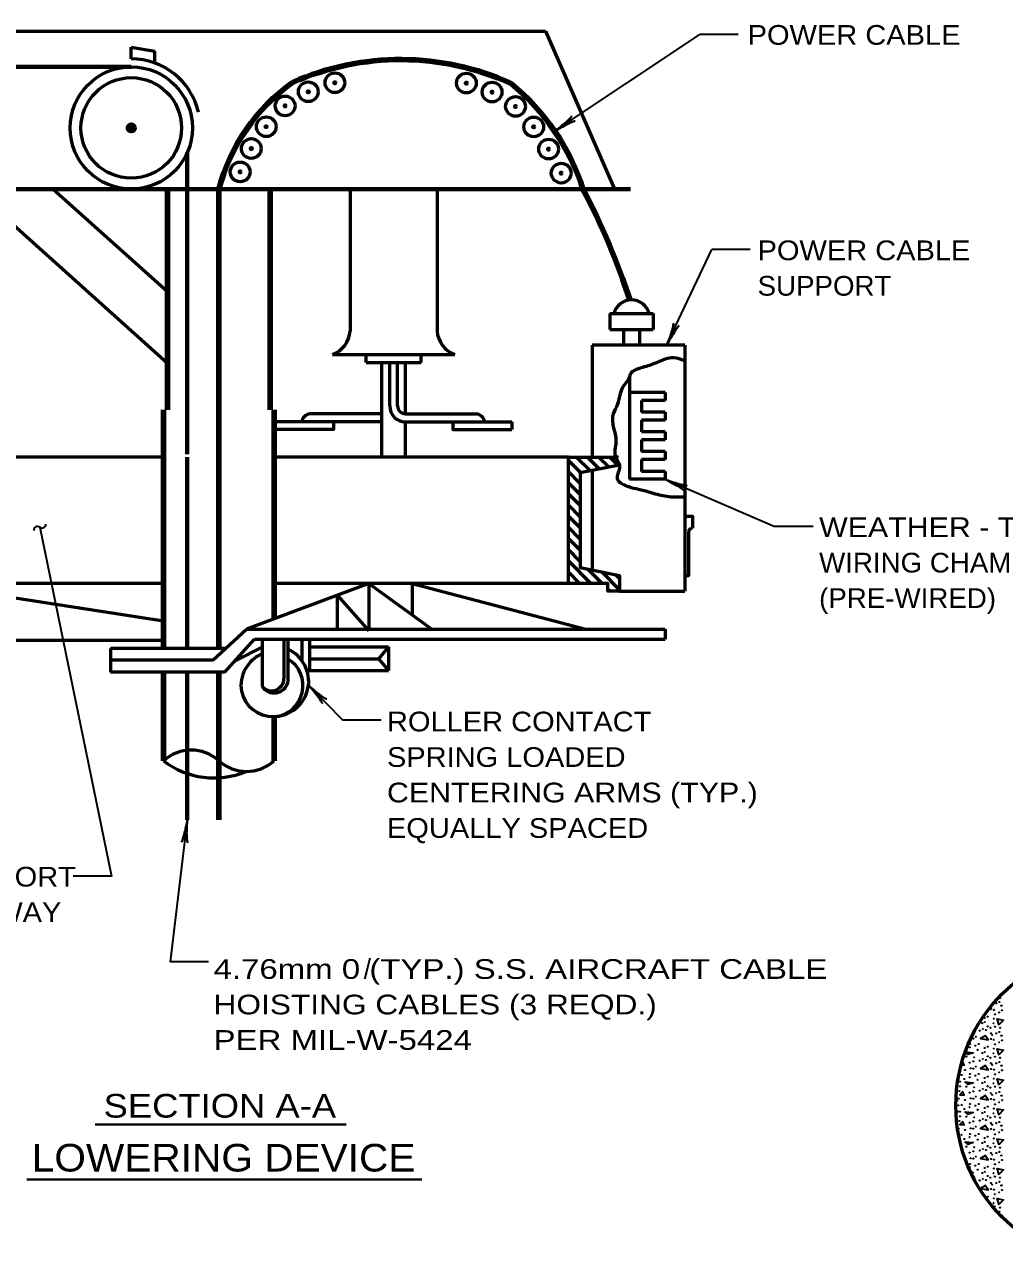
# Model space of a CAD drawing. Extents: x -24 to 689, y -7 to 446.
# Drawn here: x 208.2 to 332.4, y 109.6 to 266.6 of the extents above; entities that cross this region are included whole.
import ezdxf
from ezdxf.enums import TextEntityAlignment as Align

# ---------------------------------------------------------------- set-up
doc = ezdxf.new("R2010")
doc.units = 0
doc.header["$PDMODE"] = 32
doc.header["$PDSIZE"] = 0.5
doc.layers.add('1', color=7, linetype='Continuous', lineweight=35)

msp = doc.modelspace()

# ---------------------------------------------------------------- hatches: boundary and pattern name
at = {"layer": '1'}
for points in [[(247.661, 259.304, 1), (247.411, 259.304, 1)], [(264.325, 259.26, 1), (264.075, 259.26, 1)], [(244.293, 258.151, 1), (244.043, 258.151, 1)], [(267.586, 258.116, 1), (267.336, 258.116, 1)], [(241.357, 256.358, 1), (241.107, 256.358, 1)], [(270.557, 256.295, 1), (270.307, 256.295, 1)], [(222.233, 253.567, 1), (221.233, 253.567, 1)], [(238.965, 253.726, 1), (238.715, 253.726, 1)], [(272.86, 253.701, 1), (272.61, 253.701, 1)], [(237.069, 250.956, 1), (236.819, 250.956, 1)], [(274.748, 250.886, 1), (274.498, 250.886, 1)], [(235.657, 247.993, 1), (235.407, 247.993, 1)], [(276.345, 247.833, 1), (276.095, 247.833, 1)]]:
    msp.add_hatch(color=256, dxfattribs=at).paths.add_polyline_path(points)

# ---------------------------------------------------------------- linework, layer by layer
at = {"layer": '1', "lineweight": 53}
for p, q in [((194.233, 265.817), (274.233, 265.817)), ((274.233, 265.817), (282.983, 245.817)), ((221.733, 262.317), (221.733, 263.817)), ((221.733, 263.817), (224.733, 263.317)), ((224.733, 261.787), (224.733, 263.317)), ((201.721, 245.817), (226.335, 223.749)), ((211.835, 245.817), (226.335, 232.817)), ((249.483, 245.817), (249.483, 227.817)), ((260.483, 245.817), (260.483, 227.817)), ((282.378, 230.022), (287.878, 230.022)), ((282.378, 230.022), (282.378, 228.022)), ((287.878, 230.022), (287.878, 228.022)), ((282.378, 228.022), (287.878, 228.022)), ((284.128, 228.022), (284.128, 226.022)), ((286.128, 228.022), (286.128, 226.022)), ((247.233, 224.817), (262.733, 224.817)), ((251.483, 223.817), (251.483, 224.817)), ((258.483, 223.817), (258.483, 224.817)), ((291.878, 226.022), (280.128, 226.022)), ((280.128, 226.022), (280.128, 211.817)), ((291.878, 226.022), (291.878, 194.817)), ((251.483, 223.817), (258.483, 223.817)), ((253.483, 211.817), (253.483, 223.817)), ((254.483, 218.317), (254.483, 223.817)), ((255.483, 218.317), (255.483, 223.817)), ((256.483, 217.317), (256.483, 223.817)), ((284.878, 222.022), (284.878, 209.022)), ((289.378, 220.022), (284.878, 220.022)), ((289.378, 220.022), (289.378, 219.022)), ((289.378, 219.022), (286.378, 219.022)), ((286.378, 219.022), (286.378, 217.522)), ((253.483, 217.317), (244.353, 217.317)), ((256.483, 217.317), (265.483, 217.317)), ((289.378, 217.522), (286.378, 217.522)), ((289.378, 217.522), (289.378, 216.522)), ((239.853, 216.317), (239.853, 215.317)), ((253.483, 216.317), (239.853, 216.317)), ((256.483, 216.317), (269.983, 216.317)), ((256.483, 211.817), (256.483, 216.317)), ((269.983, 216.317), (269.983, 215.317)), ((289.378, 216.522), (286.378, 216.522)), ((286.378, 216.522), (286.378, 215.022)), ((289.378, 215.022), (286.378, 215.022)), ((289.378, 214.022), (286.378, 214.022)), ((286.378, 214.022), (286.378, 212.522)), ((289.378, 215.022), (289.378, 214.022)), ((289.378, 212.522), (286.378, 212.522)), ((289.378, 212.522), (289.378, 211.522)), ((225.835, 211.817), (196.233, 211.817)), ((277.128, 211.817), (239.835, 211.817)), ((278.707, 209.833), (277.128, 211.412)), ((279.886, 210.069), (278.137, 211.817)), ((281.064, 210.304), (279.552, 211.817)), ((282.243, 210.54), (280.966, 211.817)), ((283.421, 210.776), (282.38, 211.817)), ((289.378, 211.522), (286.378, 211.522)), ((286.378, 211.522), (286.378, 210.022)), ((278.628, 208.498), (277.128, 209.998)), ((280.128, 210.117), (280.128, 197.517)), ((289.378, 209.022), (284.878, 209.022)), ((289.378, 210.022), (286.378, 210.022)), ((289.378, 210.022), (289.378, 209.022)), ((278.628, 207.084), (277.128, 208.584)), ((278.628, 205.67), (277.128, 207.17)), ((278.628, 204.256), (277.128, 205.756)), ((278.628, 202.841), (277.128, 204.341)), ((278.628, 201.427), (277.128, 202.927)), ((278.628, 200.013), (277.128, 201.513)), ((278.628, 198.599), (277.128, 200.099)), ((279.995, 195.817), (277.128, 198.684)), ((278.581, 195.817), (277.128, 197.27)), ((281.409, 195.817), (279.605, 197.622)), ((283.628, 195.013), (281.373, 197.268)), ((283.628, 196.427), (283.14, 196.915)), ((195.233, 195.817), (225.835, 191.067)), ((225.835, 195.817), (196.233, 195.817)), ((251.835, 195.817), (236.335, 190.005)), ((277.128, 195.817), (239.835, 195.817)), ((251.835, 195.817), (251.835, 189.817)), ((251.835, 195.817), (259.828, 190.005)), ((257.335, 195.817), (257.335, 191.817)), ((257.335, 195.817), (279.328, 190.005)), ((277.167, 195.817), (277.128, 195.856)), ((282.409, 194.817), (282.128, 195.099)), ((283.628, 194.817), (291.878, 194.817)), ((247.835, 194.317), (247.835, 189.817)), ((247.835, 194.317), (251.835, 189.817)), ((225.835, 188.567), (164.733, 188.567)), ((232.085, 186.067), (236.335, 190.005)), ((233.585, 184.567), (237.335, 188.755)), ((236.335, 190.005), (289.378, 190.005)), ((237.335, 188.755), (289.378, 188.755)), ((238.335, 188.755), (238.335, 182.755)), ((241.085, 188.755), (241.085, 183.755)), ((241.585, 188.755), (241.585, 183.255)), ((243.335, 188.755), (243.335, 186.092)), ((244.335, 188.755), (244.335, 184.755)), ((289.378, 190.005), (289.378, 188.755)), ((233.704, 187.567), (219.085, 187.567)), ((219.085, 187.567), (219.085, 184.567)), ((238.335, 187.709), (234.878, 186.01)), ((244.335, 187.755), (254.335, 187.755)), ((254.335, 187.755), (254.335, 184.755)), ((232.085, 186.067), (219.085, 186.067)), ((244.335, 186.255), (253.085, 186.255)), ((233.585, 184.567), (219.085, 184.567)), ((244.016, 184.755), (254.335, 184.755))]:
    msp.add_line(p, q, dxfattribs=at)
at = {"layer": '1'}
for p, q in [((275.388, 253.162), (293.808, 265.43)), ((298.666, 265.43), (293.808, 265.43)), ((289.577, 226.022), (295.324, 238.144)), ((300.181, 238.144), (295.324, 238.144)), ((289.378, 209.022), (303.279, 203.025)), ((308.137, 203.025), (303.279, 203.025)), ((244.191, 182.927), (248.548, 178.457)), ((253.405, 178.457), (248.548, 178.457)), ((228.835, 165.817), (226.651, 147.826)), ((231.508, 147.826), (226.651, 147.826)), ((327.108, 135.18), (327.029, 135.097))]:
    msp.add_line(p, q, dxfattribs=at)
at = {"layer": '1', "lineweight": 70}
for p, q in [((200.233, 261.317), (221.733, 261.317)), ((228.835, 212.197), (228.835, 250.466)), ((239.335, 245.817), (284.983, 245.817)), ((228.835, 187.567), (228.835, 211.815)), ((228.835, 165.817), (228.835, 184.567))]:
    msp.add_line(p, q, dxfattribs=at)
at = {"layer": '1', "lineweight": 200}
for p, q in [((226.335, 217.817), (226.335, 245.817)), ((232.835, 187.567), (232.835, 245.817)), ((239.335, 217.817), (239.335, 245.817)), ((225.835, 187.567), (225.835, 217.817)), ((239.835, 191.317), (239.835, 217.817)), ((225.835, 173.317), (225.835, 184.567)), ((232.835, 165.817), (232.835, 184.567)), ((239.835, 173.317), (239.835, 178.92))]:
    msp.add_line(p, q, dxfattribs=at)
at = {"layer": '1', "lineweight": 40}
for p, q in [((217.135, 127.196), (248.977, 127.196)), ((208.484, 120.206), (258.561, 120.206))]:
    msp.add_line(p, q, dxfattribs=at)
at = {"layer": '1', "lineweight": 70}
msp.add_lwpolyline([(183.483, 245.817), (228.835, 245.817), (239.335, 245.817)], dxfattribs=at)
at = {"layer": '1', "lineweight": 53}
for points in [[(247.353, 216.317), (247.353, 215.317), (239.853, 215.317)], [(262.483, 216.317), (262.483, 215.317), (269.983, 215.317)], [(277.128, 195.817), (277.128, 211.817), (283.128, 211.817)], [(283.628, 210.817), (278.628, 209.817), (278.628, 197.817), (283.628, 196.817), (283.628, 194.817), (282.128, 194.817), (282.128, 195.817), (277.128, 195.817)], [(291.878, 204.317), (292.878, 204.317), (292.878, 202.817)], [(291.878, 196.817), (292.378, 196.817), (292.378, 202.317)], [(254.335, 187.755), (253.085, 186.255), (254.335, 184.755)]]:
    msp.add_lwpolyline(points, dxfattribs=at)
at = {"layer": '1'}
for points in [[(210.138, 202.928), (219.214, 158.699), (214.356, 158.699)], [(331.728, 139.8), (331.488, 140.6), (332.268, 140.44), (331.708, 139.84)], [(330.008, 138.46), (329.348, 138.1), (330.328, 137.92), (329.968, 138.48)], [(331.728, 136), (331.488, 136.8), (332.268, 136.64), (331.708, 136.04)], [(326.94, 134.765), (327.308, 134.74), (327.108, 135.14)], [(327.454, 136.412), (328.428, 136.3), (327.748, 136.06), (327.438, 136.37)], [(330.008, 134.66), (329.348, 134.3), (330.328, 134.12), (329.968, 134.68)], [(331.728, 132.2), (331.488, 133), (332.268, 132.84), (331.708, 132.24)], [(327.108, 131.38), (326.728, 130.98), (327.308, 130.94), (327.108, 131.34)], [(330.008, 130.86), (329.348, 130.5), (330.328, 130.32), (329.968, 130.88)], [(331.728, 128.4), (331.488, 129.2), (332.268, 129.04), (331.708, 128.44)], [(327.108, 127.58), (326.728, 127.18), (327.308, 127.14), (327.108, 127.54)], [(330.008, 127.06), (329.348, 126.7), (330.328, 126.52), (329.968, 127.08)], [(331.728, 124.6), (331.488, 125.4), (332.268, 125.24), (331.708, 124.64)], [(327.247, 123.344), (327.308, 123.34), (327.157, 123.641)], [(330.008, 123.26), (329.348, 122.9), (330.328, 122.72), (329.968, 123.28)], [(328.138, 121.133), (328.428, 121.1), (328.197, 121.018)], [(331.728, 120.8), (331.488, 121.6), (332.268, 121.44), (331.708, 120.84)], [(330.008, 119.46), (329.348, 119.1), (330.328, 118.92), (329.968, 119.48)], [(331.728, 117), (331.488, 117.8), (332.268, 117.64), (331.708, 117.04)]]:
    msp.add_lwpolyline(points, dxfattribs=at)
for points in [[(327.388, 132.62), (328.428, 132.5), (327.748, 132.26)], [(327.388, 128.82), (328.428, 128.7), (327.748, 128.46)], [(327.388, 125.02), (328.428, 124.9), (327.748, 124.66)]]:
    msp.add_lwpolyline(points, close=True, dxfattribs=at)
at = {"layer": '1', "lineweight": 53}
for centre, radius in [((221.733, 253.567), 7.75), ((221.733, 253.567), 6.375), ((244.168, 258.151), 1.25), ((247.536, 259.304), 1.25), ((247.536, 259.304), 0.125), ((264.2, 259.26), 1.25), ((264.2, 259.26), 0.125), ((267.461, 258.116), 1.25), ((241.232, 256.358), 1.25), ((244.168, 258.151), 0.125), ((267.461, 258.116), 0.125), ((241.232, 256.358), 0.125), ((270.432, 256.295), 1.25), ((270.432, 256.295), 0.125), ((238.84, 253.726), 1.25), ((272.735, 253.701), 1.25), ((221.733, 253.567), 0.5), ((238.84, 253.726), 0.125), ((272.735, 253.701), 0.125), ((236.944, 250.956), 1.25), ((274.623, 250.886), 1.25), ((236.944, 250.956), 0.125), ((274.623, 250.886), 0.125), ((235.532, 247.993), 1.25), ((276.22, 247.833), 1.25), ((235.532, 247.993), 0.125), ((276.22, 247.833), 0.125), ((346.236, 129.608), 20)]:
    msp.add_circle(centre, radius, dxfattribs=at)
at = {"layer": '1'}
for centre in [(331.849, 143.256), (330.683, 141.829), (331.067, 141.737), (331.359, 142.572), (331.73, 141.405), (331.756, 142.731), (331.982, 142.267), (332.035, 142.267), (332.101, 141.684), (329.596, 140.053), (329.874, 140.689), (329.914, 140.199), (330.285, 140.862), (331.014, 140.026), (331.054, 140.623), (331.187, 141.167), (328.774, 138.321), (329.265, 139.103), (329.662, 139.297), (330.06, 139.17), (330.259, 139.655), (330.617, 139.456), (330.683, 138.772), (330.842, 138.56), (331.2, 139.602), (331.359, 138.772), (331.756, 138.931), (331.849, 139.456), (331.982, 138.467), (332.035, 138.467), (327.979, 136.995), (328.032, 137.393), (328.456, 138.083), (328.721, 137.181), (329, 136.664), (329.119, 137.393), (329.874, 136.889), (330.285, 137.062), (330.683, 138.029), (331.054, 136.823), (331.067, 137.937), (331.187, 137.367), (331.73, 137.605), (332.101, 137.884), (327.569, 135.802), (328.006, 135.038), (328.456, 135.21), (328.562, 135.723), (329.265, 135.303), (329.596, 136.253), (329.662, 135.497), (329.914, 136.399), (330.06, 135.37), (330.259, 135.855), (330.617, 135.656), (331.014, 136.226), (331.2, 135.802), (331.756, 135.131), (331.849, 135.656), (326.972, 133.487), (327.396, 134.097), (328.032, 133.593), (328.112, 134.322), (328.456, 134.283), (328.774, 134.521), (329.119, 133.593), (330.683, 134.972), (330.683, 134.229), (330.842, 134.76), (331.067, 134.137), (331.187, 133.567), (331.359, 134.972), (331.73, 133.805), (331.982, 134.667), (332.035, 134.667), (332.101, 134.084), (326.534, 132.623), (326.76, 132.639), (326.76, 132.042), (327.303, 132.97), (327.569, 132.002), (327.979, 133.195), (328.562, 131.923), (328.721, 133.381), (329, 132.864), (329.596, 132.453), (329.874, 133.089), (329.914, 132.599), (330.259, 132.055), (330.285, 133.262), (331.014, 132.426), (331.054, 133.023), (331.2, 132.002), (326.381, 130.549), (326.614, 130.469), (326.667, 131.45), (328.006, 131.238), (328.112, 130.522), (328.456, 131.41), (328.456, 130.483), (328.774, 130.721), (329.265, 131.503), (329.662, 131.697), (330.06, 131.57), (330.617, 131.856), (330.683, 131.172), (330.683, 130.429), (330.842, 130.96), (331.067, 130.337), (331.359, 131.172), (331.756, 131.331), (331.849, 131.856), (331.982, 130.867), (332.035, 130.867), (326.395, 130.231), (326.534, 128.823), (326.554, 129.634), (326.76, 128.839), (326.972, 129.687), (327.303, 129.17), (327.396, 130.297), (327.979, 129.395), (328.032, 129.793), (328.721, 129.581), (329, 129.064), (329.119, 129.793), (329.874, 129.289), (329.914, 128.799), (330.285, 129.462), (331.054, 129.223), (331.187, 129.767), (331.73, 130.005), (332.101, 130.284), (326.667, 127.65), (326.76, 128.242), (327.569, 128.202), (328.006, 127.438), (328.456, 127.61), (328.562, 128.123), (329.265, 127.703), (329.596, 128.653), (329.662, 127.897), (330.06, 127.77), (330.259, 128.255), (330.617, 128.056), (330.683, 127.372), (331.014, 128.626), (331.2, 128.202), (331.359, 127.372), (331.756, 127.531), (331.849, 128.056), (326.614, 126.669), (326.972, 125.887), (327.396, 126.497), (328.032, 125.993), (328.112, 126.722), (328.456, 126.683), (328.721, 125.781), (328.774, 126.921), (329.119, 125.993), (330.285, 125.662), (330.683, 126.629), (330.842, 127.16), (331.067, 126.537), (331.187, 125.967), (331.73, 126.205), (331.982, 127.067), (332.035, 127.067), (332.101, 126.484), (327.303, 125.37), (327.569, 124.402), (327.979, 125.595), (328.562, 124.323), (329, 125.264), (329.596, 124.853), (329.662, 124.097), (329.874, 125.489), (329.914, 124.999), (330.259, 124.455), (330.617, 124.256), (331.014, 124.826), (331.054, 125.423), (331.2, 124.402), (331.849, 124.256), (328.006, 123.638), (328.112, 122.922), (328.456, 123.81), (328.456, 122.883), (328.774, 123.121), (329.265, 123.903), (330.06, 123.97), (330.683, 123.572), (330.683, 122.829), (330.842, 123.36), (331.067, 122.737), (331.359, 123.572), (331.756, 123.731), (331.982, 123.267), (332.035, 123.267), (332.101, 122.684), (327.979, 121.795), (328.032, 122.193), (328.721, 121.981), (329, 121.464), (329.119, 122.193), (329.596, 121.053), (329.874, 121.689), (329.914, 121.199), (330.285, 121.862), (331.014, 121.026), (331.054, 121.623), (331.187, 122.167), (331.73, 122.405), (328.562, 120.523), (329.265, 120.103), (329.662, 120.297), (330.06, 120.17), (330.259, 120.655), (330.617, 120.456), (330.683, 119.772), (330.842, 119.56), (331.2, 120.602), (331.359, 119.772), (331.756, 119.931), (331.849, 120.456), (331.982, 119.467), (332.035, 119.467), (330.285, 118.062), (330.683, 119.029), (331.054, 117.823), (331.067, 118.937), (331.187, 118.367), (331.73, 118.605), (332.101, 118.884), (331.014, 117.226), (331.2, 116.802), (331.849, 116.656), (331.756, 116.131), (331.982, 115.667), (332.035, 115.667)]:
    msp.add_circle(centre, 0.0265, dxfattribs=at)
at = {"layer": '1', "lineweight": 53}
for centre, radius, start, end in [((221.733, 253.567), 8.75, 13.21298, 90), ((285.128, 229.451), 2.321, 14.25003, 165.74997), ((245.99, 228.093), 3.503, 290.77405, 355.48615), ((263.976, 228.093), 3.503, 184.51385, 249.22595), ((256.483, 218.317), 2, 180, 270), ((256.483, 218.317), 1, 180, 270), ((244.55, 216.084), 1.249, 99.06756, 169.23059), ((265.286, 216.084), 1.249, 10.76941, 80.93244), ((292.839, 202.356), 0.463, 85.16169, 184.83831), ((239.511, 182.858), 3.98, 274.66923, 58.59072), ((239.532, 183.745), 1.553, 219.60119, 0.36502), ((239.851, 183.714), 1.794, 212.33384, 345.15848), ((229.335, 169.452), 5.214, 47.83573, 132.16427), ((232.217, 181.616), 10.469, 232.43894, 292.84425), ((236.335, 177.182), 5.214, 227.83573, 312.16427)]:
    msp.add_arc(centre, radius, start, end, dxfattribs=at)
at = {"layer": '1', "lineweight": 200}
for centre, radius, start, end in [((255.869, 228.426), 33.811, 65.5326, 113.9223), ((256.284, 239.614), 24.255, 125.61654, 165.18227), ((251.591, 236.963), 28.788, 17.9133, 50.57589), ((199.037, 203.822), 90.305, 18.02279, 27.71258)]:
    msp.add_arc(centre, radius, start, end, dxfattribs=at)
at = {"layer": '1'}
for centre, radius, start, end in [((209.85, 202.53), 0.49, 54.13935, 179.72998), ((210.425, 203.325), 0.49, 234.13935, 359.72998), ((330.842, 142.36), 0.0265, 266.58029, 15.42037), ((326.302, 127.964), 0.0265, 322.82051, 43.18034), ((326.76, 125.039), 0.0265, 342.53248, 47.46843)]:
    msp.add_arc(centre, radius, start, end, dxfattribs=at)
at = {"layer": '1', "lineweight": 40}
for centre, major_axis, ratio, start_param, end_param in [((276.143, 253.997), (-1.4, -1.12), 0.122415, 0.8963533, 3.1415927), ((276.438, 253.607), (-1.559, -0.827), 0.07063, 3.1407148, 5.41811), ((289.795, 227.126), (-0.624, -1.68), 0.122415, 0.8963533, 3.1415927), ((289.795, 227.126), (-0.624, -1.68), 0.122415, 0.8963533, 3.1415927), ((290.248, 226.944), (0.911, 1.512), 0.07063, 6.2823074, 8.5597026), ((290.248, 226.944), (0.911, 1.512), 0.07063, 6.2823074, 8.5597026), ((290.323, 208.384), (-1.543, 0.857), 0.07063, 3.1407148, 5.41811), ((290.323, 208.384), (-1.543, 0.857), 0.07063, 3.1407148, 5.41811), ((290.489, 208.843), (-1.702, 0.564), 0.122415, 0.8963533, 3.1415927), ((290.489, 208.843), (-1.702, 0.564), 0.122415, 0.8963533, 3.1415927), ((244.822, 181.977), (1.1, -1.38), 0.07063, 6.2823074, 8.5597026), ((244.822, 181.977), (1.1, -1.38), 0.07063, 6.2823074, 8.5597026), ((245.151, 182.338), (-1.358, 1.17), 0.122415, 0.8963533, 3.1415927), ((245.151, 182.338), (-1.358, 1.17), 0.122415, 0.8963533, 3.1415927), ((228.49, 164.73), (-0.386, -1.722), 0.07063, 6.2823074, 8.5597026), ((228.49, 164.73), (-0.386, -1.722), 0.07063, 6.2823074, 8.5597026), ((228.978, 164.7), (0.06, 1.792), 0.122415, 0.8963533, 3.1415927), ((228.978, 164.7), (0.06, 1.792), 0.122415, 0.8963533, 3.1415927)]:
    msp.add_ellipse(centre, major_axis=major_axis, ratio=ratio, start_param=start_param, end_param=end_param, dxfattribs=at)
at = {"layer": '1', "lineweight": 53}
for centre, major_axis, ratio, start_param, end_param in [((240.07, 183.134), (4.092, 1.858), 0.924461, 1.5748771, 4.2621165), ((239.727, 183.413), (4.092, -1.858), 0.992304, 5.1626615, 7.8539816)]:
    msp.add_ellipse(centre, major_axis=major_axis, ratio=ratio, start_param=start_param, end_param=end_param, dxfattribs=at)
msp.add_spline([(291.878, 224.022), (290.48, 224.413), (288.373, 223.838), (286.792, 223.263), (284.972, 222.304), (284.878, 222.022), (283.966, 220.579), (283.343, 218.519), (282.816, 217.321), (282.816, 215.692), (283.103, 214.494), (283.151, 213.775), (283.128, 211.817), (283.628, 210.817), (283.343, 209.559), (283.343, 208.984), (283.822, 208.505), (286.361, 207.69), (287.894, 207.259), (289.857, 206.827), (291.878, 206.817)], degree=3, dxfattribs=at)
at = {"layer": '1'}
msp.add_point((283.128, 211.817), dxfattribs=at)

# ---------------------------------------------------------------- texts
for s, height, width, p in [('POWER CABLE', 2.5, 1.1, (313.339, 264.111)), ('SECTION A-A', 3, 1.15, (232.955, 128.074)), ('LOWERING DEVICE', 3.5, 1.1, (233.431, 121.239))]:
    msp.add_text(s, height=height, dxfattribs=dict(at, width=width)).set_placement(p, align=Align.CENTER)
for s, width, p in [('POWER CABLE', 1.1, (301.109, 236.797)), ('SUPPORT', 1.05, (301.109, 232.297)), ('WEATHER - TIGHT', 1.15, (308.907, 201.691)), ('WIRING CHAMBER', 1.05, (308.907, 197.191)), ('(PRE-WIRED)', 1.05, (308.907, 192.691)), ('ROLLER CONTACT', 1.1, (254.138, 177.046)), ('SPRING LOADED', 1.1, (254.138, 172.546)), ('CENTERING ARMS (TYP.)', 1.15, (254.138, 168.046)), ('EQUALLY SPACED', 1.1, (254.138, 163.546)), ('LUMINAIRE SUPPORT', 1.1, (175.89, 157.371)), ('RING AND WIREWAY', 1.1, (175.89, 152.871)), ('4.76mm 0 (TYP.) S.S. AIRCRAFT CABLE', 1.25, (232.159, 145.663)), ('HOISTING CABLES (3 REQD.)', 1.2, (232.159, 141.163)), ('PER MIL-W-5424', 1.25, (232.159, 136.663))]:
    msp.add_text(s, height=2.5, dxfattribs=dict(at, width=width)).set_placement(p)
msp.add_text('/', height=2.5, dxfattribs=at).set_placement((251.651, 145.667), align=Align.CENTER)

doc.saveas('drawing.dxf')
